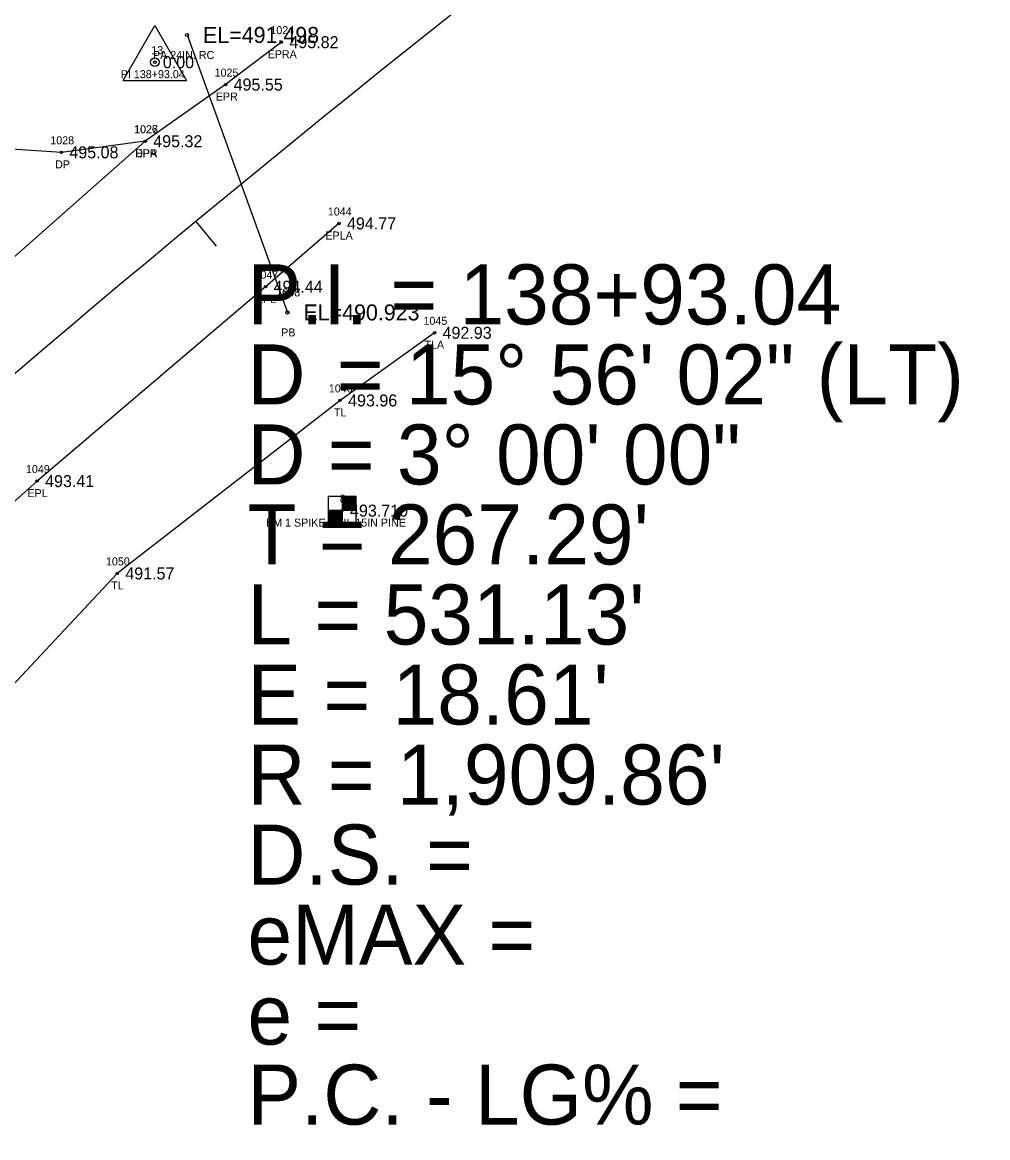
# Model space of a CAD drawing. Extents: x 1740701 to 1743138, y 748181 to 751839.
# Drawn here: x 1742062.9 to 1742183.5, y 750456.4 to 750595.8 of the extents above; entities that cross this region are included whole.
import ezdxf

# ---------------------------------------------------------------- set-up
doc = ezdxf.new("R2010")
doc.units = 0
for name, color, linetype in [('RD_EX_DR_Pipe', 7, 'Continuous'), ('RD_EX_DR_Pipe_txCode', 7, 'Continuous'), ('RD_EX_Driveway', 7, 'Continuous'), ('RD_EX_Driveway_txCode', 7, 'Continuous'), ('RD_EX_Road', 7, 'Continuous'), ('RD_EX_Road_txCode', 7, 'Continuous'), ('RD_EX_TX_Driveway_ELEV', 7, 'Continuous'), ('RD_EX_TX_Road_ELEV', 7, 'Continuous'), ('RD_EX_TX_VEG_ELEV', 7, 'Continuous'), ('RD_EX_VEG', 7, 'Continuous'), ('RD_EX_VEG_txCode', 7, 'Continuous'), ('RD_HC_Cl', 7, 'Continuous'), ('RD_HC_Data', 7, 'Continuous'), ('RD_HC_Data_Tic', 7, 'Continuous'), ('RD_HC_Survey', 7, 'Continuous'), ('RD_HC_Survey_ELEV', 7, 'Continuous'), ('RD_HC_Survey_txCode', 7, 'Continuous'), ('RD_HC_txCode', 7, 'Continuous'), ('RD_SMD_Locator', 7, 'Continuous'), ('RD_TX_Pipe_ElevEX', 7, 'Continuous')]:
    doc.layers.add(name, color=color, linetype=linetype)

msp = doc.modelspace()

# ---------------------------------------------------------------- linework, layer by layer
at = {"layer": 'RD_EX_DR_Pipe'}
msp.add_line((1742083.45, 750594.17), (1742095.99, 750559.5), dxfattribs=at)
at = {"layer": 'RD_EX_Driveway'}
msp.add_lwpolyline([(1742078.23, 750580.89), (1742067.75, 750579.5), (1742055.26, 750580.31), (1742043.56, 750582.25), (1742032.68, 750586.37), (1742011.54, 750590.38), (1741988.47, 750592.64), (1741971.4, 750592.74)], dxfattribs=at)
at = {"layer": 'RD_EX_Road'}
for points in [[(1742095.24, 750593.27), (1742088.27, 750587.97), (1742078.23, 750580.89), (1742049.13, 750555.21), (1742012.94, 750522.73), (1741975.54, 750488.03), (1741940.71, 750452.82), (1741916.22, 750428.67), (1741904.72, 750416.99), (1741884.38, 750395.02), (1741870.75, 750380.27), (1741817.36, 750322.98), (1741803.89, 750307.66), (1741783.86, 750287.33), (1741735.44, 750234.07), (1741718.84, 750214.98), (1741710.25, 750205.58), (1741668.97, 750159.8), (1741635, 750122.49), (1741604.35, 750087.7), (1741600.63, 750085.47)], [(1742102.43, 750570.61), (1742093.26, 750562.71), (1742064.72, 750538.42), (1742027.92, 750505.65), (1741991.25, 750471.83), (1741956.32, 750436.98), (1741921.43, 750401.39), (1741886.79, 750364.93), (1741819.64, 750292.67), (1741751.78, 750219.01), (1741684.42, 750145.59), (1741650.98, 750108.5), (1741637.17, 750092.42), (1741621.17, 750073.94), (1741621.31, 750072.22), (1741619.24, 750070.27)]]:
    msp.add_lwpolyline(points, dxfattribs=at)
at = {"layer": 'RD_EX_VEG'}
msp.add_lwpolyline([(1742114.37, 750556.95), (1742102.57, 750548.5), (1742074.74, 750526.88), (1742042.48, 750492.43), (1742005.49, 750457.25), (1741971.49, 750420.27), (1741936.96, 750386.65), (1741902.94, 750350.76), (1741835.15, 750278.46), (1741766.69, 750206.43), (1741693.82, 750135.64), (1741661.95, 750096.11), (1741631.51, 750044.18), (1741602.3, 750028.04), (1741573.25, 749982.32), (1741544.84, 749941.06), (1741514.68, 749901.47), (1741495.89, 749858.02), (1741462.75, 749819.18), (1741434.73, 749775.9), (1741408.39, 749735.06), (1741355.53, 749651.67)], dxfattribs=at)
at = {"layer": 'RD_HC_Cl'}
msp.add_arc((1743302.33, 749099.61), 1909.86, 121.38831, 137.32219, dxfattribs=at)
at = {"layer": 'RD_HC_Data'}
for p, q in [((1742075.46, 750588.47), (1742079.44, 750595.35)), ((1742079.44, 750595.35), (1742083.4, 750588.47)), ((1742075.46, 750588.47), (1742083.4, 750588.47))]:
    msp.add_line(p, q, dxfattribs=at)
msp.add_circle((1742079.43, 750590.77), 0.529, dxfattribs=at)
at = {"layer": 'RD_HC_Data_Tic'}
msp.add_line((1742084.54, 750570.85), (1742087.09, 750567.77), dxfattribs=at)
at = {"layer": 'RD_HC_Survey'}
for p, q in [((1742102.81, 750536.48), (1742102.81, 750532.98)), ((1742102.83, 750536.48), (1742102.83, 750534.73)), ((1742102.85, 750536.48), (1742102.85, 750534.73)), ((1742102.87, 750536.48), (1742102.87, 750534.73)), ((1742102.9, 750536.48), (1742102.9, 750534.73)), ((1742102.92, 750536.48), (1742102.92, 750534.73)), ((1742102.95, 750536.48), (1742102.95, 750534.73)), ((1742102.97, 750536.48), (1742102.97, 750534.73)), ((1742103, 750536.48), (1742103, 750534.73)), ((1742103.02, 750536.48), (1742103.02, 750534.73)), ((1742103.05, 750536.48), (1742103.05, 750534.73)), ((1742103.07, 750536.48), (1742103.07, 750534.73)), ((1742103.1, 750536.48), (1742103.1, 750534.73)), ((1742103.12, 750536.48), (1742103.12, 750534.73)), ((1742103.15, 750536.48), (1742103.15, 750534.73)), ((1742103.17, 750536.48), (1742103.17, 750534.73)), ((1742103.2, 750536.48), (1742103.2, 750534.73)), ((1742103.22, 750536.48), (1742103.22, 750534.73)), ((1742103.25, 750536.48), (1742103.25, 750534.73)), ((1742103.27, 750536.48), (1742103.27, 750534.73)), ((1742103.3, 750536.48), (1742103.3, 750534.73)), ((1742103.32, 750536.48), (1742103.32, 750534.73)), ((1742103.34, 750536.48), (1742103.34, 750534.73)), ((1742103.37, 750536.48), (1742103.37, 750534.73)), ((1742103.39, 750536.48), (1742103.39, 750534.73)), ((1742103.42, 750536.48), (1742103.42, 750534.73)), ((1742103.44, 750536.48), (1742103.44, 750534.73)), ((1742103.47, 750536.48), (1742103.47, 750534.73)), ((1742103.49, 750536.48), (1742103.49, 750534.73)), ((1742103.52, 750536.48), (1742103.52, 750534.73)), ((1742103.54, 750536.48), (1742103.54, 750534.73)), ((1742103.57, 750536.48), (1742103.57, 750534.73)), ((1742103.59, 750536.48), (1742103.59, 750534.73)), ((1742103.62, 750536.48), (1742103.62, 750534.73)), ((1742103.64, 750536.48), (1742103.64, 750534.73)), ((1742103.67, 750536.48), (1742103.67, 750534.73)), ((1742103.69, 750536.48), (1742103.69, 750534.73)), ((1742103.72, 750536.48), (1742103.72, 750534.73)), ((1742103.74, 750536.48), (1742103.74, 750534.73)), ((1742103.77, 750536.48), (1742103.77, 750534.73)), ((1742103.79, 750536.48), (1742103.79, 750534.73)), ((1742103.82, 750536.48), (1742103.82, 750534.73)), ((1742103.84, 750536.48), (1742103.84, 750534.73)), ((1742103.86, 750536.48), (1742103.86, 750534.73)), ((1742103.89, 750536.48), (1742103.89, 750534.73)), ((1742103.91, 750536.48), (1742103.91, 750534.73)), ((1742103.94, 750536.48), (1742103.94, 750534.73)), ((1742103.96, 750536.48), (1742103.96, 750534.73)), ((1742103.99, 750536.48), (1742103.99, 750534.73)), ((1742104.01, 750536.48), (1742104.01, 750534.73)), ((1742104.04, 750536.48), (1742104.04, 750534.73)), ((1742104.06, 750536.48), (1742104.06, 750534.73)), ((1742104.09, 750536.48), (1742104.09, 750534.73)), ((1742104.11, 750536.48), (1742104.11, 750534.73)), ((1742104.14, 750536.48), (1742104.14, 750534.73)), ((1742104.16, 750536.48), (1742104.16, 750534.73)), ((1742104.19, 750536.48), (1742104.19, 750534.73)), ((1742104.21, 750536.48), (1742104.21, 750534.73)), ((1742104.24, 750536.48), (1742104.24, 750534.73)), ((1742104.26, 750536.48), (1742104.26, 750534.73)), ((1742104.29, 750536.48), (1742104.29, 750534.73)), ((1742104.31, 750536.48), (1742104.31, 750534.73)), ((1742104.33, 750536.48), (1742104.33, 750534.73)), ((1742104.36, 750536.48), (1742104.36, 750534.73)), ((1742104.38, 750536.48), (1742104.38, 750534.73)), ((1742104.41, 750536.48), (1742104.41, 750534.73)), ((1742104.43, 750536.48), (1742104.43, 750534.73)), ((1742104.46, 750536.48), (1742104.46, 750534.73)), ((1742104.48, 750536.48), (1742104.48, 750534.73)), ((1742104.51, 750536.48), (1742104.51, 750534.73)), ((1742104.53, 750536.48), (1742104.53, 750534.73)), ((1742104.56, 750534.73), (1742101.06, 750534.73)), ((1742101.06, 750534.73), (1742101.06, 750532.98)), ((1742101.08, 750534.73), (1742101.08, 750532.98)), ((1742101.11, 750534.73), (1742101.11, 750532.98)), ((1742101.13, 750534.73), (1742101.13, 750532.98)), ((1742101.16, 750534.73), (1742101.16, 750532.98)), ((1742101.18, 750534.73), (1742101.18, 750532.98)), ((1742101.21, 750534.73), (1742101.21, 750532.98)), ((1742101.23, 750534.73), (1742101.23, 750532.98)), ((1742101.26, 750534.73), (1742101.26, 750532.98)), ((1742101.28, 750534.73), (1742101.28, 750532.98)), ((1742101.3, 750534.73), (1742101.3, 750532.98)), ((1742101.33, 750534.73), (1742101.33, 750532.98)), ((1742101.35, 750534.73), (1742101.35, 750532.98)), ((1742101.38, 750534.73), (1742101.38, 750532.98)), ((1742101.4, 750534.73), (1742101.4, 750532.98)), ((1742101.43, 750534.73), (1742101.43, 750532.98)), ((1742101.45, 750534.73), (1742101.45, 750532.98)), ((1742101.48, 750534.73), (1742101.48, 750532.98)), ((1742101.5, 750534.73), (1742101.5, 750532.98)), ((1742101.53, 750534.73), (1742101.53, 750532.98)), ((1742101.55, 750534.73), (1742101.55, 750532.98)), ((1742101.58, 750534.73), (1742101.58, 750532.98)), ((1742101.6, 750534.73), (1742101.6, 750532.98)), ((1742101.63, 750534.73), (1742101.63, 750532.98)), ((1742101.65, 750534.73), (1742101.65, 750532.98)), ((1742101.68, 750534.73), (1742101.68, 750532.98)), ((1742101.7, 750534.73), (1742101.7, 750532.98)), ((1742101.73, 750534.73), (1742101.73, 750532.98)), ((1742101.75, 750534.73), (1742101.75, 750532.98)), ((1742101.78, 750534.73), (1742101.78, 750532.98)), ((1742101.8, 750534.73), (1742101.8, 750532.98)), ((1742101.82, 750534.73), (1742101.82, 750532.98)), ((1742101.85, 750534.73), (1742101.85, 750532.98)), ((1742101.87, 750534.73), (1742101.87, 750532.98)), ((1742101.9, 750534.73), (1742101.9, 750532.98)), ((1742101.92, 750534.73), (1742101.92, 750532.98)), ((1742101.95, 750534.73), (1742101.95, 750532.98)), ((1742101.97, 750534.73), (1742101.97, 750532.98)), ((1742102, 750534.73), (1742102, 750532.98)), ((1742102.02, 750534.73), (1742102.02, 750532.98)), ((1742102.05, 750534.73), (1742102.05, 750532.98)), ((1742102.07, 750534.73), (1742102.07, 750532.98)), ((1742102.1, 750534.73), (1742102.1, 750532.98)), ((1742102.12, 750534.73), (1742102.12, 750532.98)), ((1742102.15, 750534.73), (1742102.15, 750532.98)), ((1742102.17, 750534.73), (1742102.17, 750532.98)), ((1742102.2, 750534.73), (1742102.2, 750532.98)), ((1742102.22, 750534.73), (1742102.22, 750532.98)), ((1742102.25, 750534.73), (1742102.25, 750532.98)), ((1742102.27, 750534.73), (1742102.27, 750532.98)), ((1742102.29, 750534.73), (1742102.29, 750532.98)), ((1742102.32, 750534.73), (1742102.32, 750532.98)), ((1742102.34, 750534.73), (1742102.34, 750532.98)), ((1742102.37, 750534.73), (1742102.37, 750532.98)), ((1742102.39, 750534.73), (1742102.39, 750532.98)), ((1742102.42, 750534.73), (1742102.42, 750532.98)), ((1742102.44, 750534.73), (1742102.44, 750532.98)), ((1742102.47, 750534.73), (1742102.47, 750532.98)), ((1742102.49, 750534.73), (1742102.49, 750532.98)), ((1742102.52, 750534.73), (1742102.52, 750532.98)), ((1742102.54, 750534.73), (1742102.54, 750532.98)), ((1742102.57, 750534.73), (1742102.57, 750532.98)), ((1742102.59, 750534.73), (1742102.59, 750532.98)), ((1742102.62, 750534.73), (1742102.62, 750532.98)), ((1742102.64, 750534.73), (1742102.64, 750532.98)), ((1742102.67, 750534.73), (1742102.67, 750532.98)), ((1742102.69, 750534.73), (1742102.69, 750532.98)), ((1742102.72, 750534.73), (1742102.72, 750532.98)), ((1742102.74, 750534.73), (1742102.74, 750532.98)), ((1742102.77, 750534.73), (1742102.77, 750532.98)), ((1742102.79, 750534.73), (1742102.79, 750532.98))]:
    msp.add_line(p, q, dxfattribs=at)
msp.add_lwpolyline([(1742104.56, 750536.48), (1742101.06, 750536.48), (1742101.06, 750532.98), (1742104.56, 750532.98)], close=True, dxfattribs=at)
at = {"layer": 'RD_SMD_Locator'}
for centre, radius in [((1742083.45, 750594.17), 0.2), ((1742095.24, 750593.27), 0.15), ((1742079.43, 750590.77), 0.15), ((1742088.27, 750587.97), 0.15), ((1742078.23, 750580.89), 0.15), ((1742078.23, 750580.89), 0.15), ((1742067.75, 750579.5), 0.15), ((1742102.43, 750570.61), 0.15), ((1742093.26, 750562.71), 0.15), ((1742095.99, 750559.5), 0.2), ((1742114.37, 750556.95), 0.15), ((1742102.57, 750548.5), 0.15), ((1742064.72, 750538.42), 0.15), ((1742102.81, 750534.73), 0.15), ((1742074.74, 750526.88), 0.15)]:
    msp.add_circle(centre, radius, dxfattribs=at)

# ---------------------------------------------------------------- texts
at = {"layer": 'RD_EX_DR_Pipe_txCode'}
for s, p in [('PA 24IN. RC', (1742079.2, 750591.17)), ('1048', (1742094.61, 750561.5)), ('PB', (1742095.21, 750556.5))]:
    msp.add_text(s, height=1, dxfattribs=at).set_placement(p)
at = {"layer": 'RD_EX_Driveway_txCode'}
for s, p in [('1027', (1742076.85, 750581.89)), ('1028', (1742066.37, 750580.5)), ('DPA', (1742076.97, 750578.89)), ('DP', (1742066.97, 750577.5))]:
    msp.add_text(s, height=1, dxfattribs=at).set_placement(p)
at = {"layer": 'RD_EX_Road_txCode'}
for s, p in [('1024', (1742093.86, 750594.27)), ('EPRA', (1742093.52, 750591.27)), ('1025', (1742086.89, 750588.97)), ('EPR', (1742087.04, 750585.97)), ('1026', (1742076.83, 750581.89)), ('EPR', (1742077.01, 750578.89)), ('1044', (1742101.04, 750571.61)), ('EPLA', (1742100.73, 750568.61)), ('1047', (1742091.88, 750563.71)), ('EPL', (1742092.06, 750560.71)), ('1049', (1742063.33, 750539.42)), ('EPL', (1742063.52, 750536.42))]:
    msp.add_text(s, height=1, dxfattribs=at).set_placement(p)
at = {"layer": 'RD_EX_TX_Driveway_ELEV'}
for s, p in [('495.32', (1742079.23, 750580.14)), ('495.08', (1742068.75, 750578.75))]:
    msp.add_text(s, height=1.5, dxfattribs=at).set_placement(p)
at = {"layer": 'RD_EX_TX_Road_ELEV'}
for s, p in [('495.82', (1742096.24, 750592.52)), ('495.55', (1742089.27, 750587.22)), ('495.32', (1742079.23, 750580.14)), ('494.77', (1742103.43, 750569.86)), ('494.44', (1742094.26, 750561.96)), ('493.41', (1742065.72, 750537.67))]:
    msp.add_text(s, height=1.5, dxfattribs=at).set_placement(p)
at = {"layer": 'RD_EX_TX_VEG_ELEV'}
for s, p in [('492.93', (1742115.37, 750556.2)), ('493.96', (1742103.57, 750547.75)), ('491.57', (1742075.74, 750526.13))]:
    msp.add_text(s, height=1.5, dxfattribs=at).set_placement(p)
at = {"layer": 'RD_EX_VEG_txCode'}
for s, p in [('1045', (1742112.99, 750557.95)), ('TLA', (1742113.11, 750554.95)), ('1046', (1742101.16, 750549.5)), ('TL', (1742101.8, 750546.5)), ('1050', (1742073.32, 750527.88)), ('TL', (1742073.97, 750524.88))]:
    msp.add_text(s, height=1, dxfattribs=at).set_placement(p)
at = {"layer": 'RD_HC_Data'}
for s, p in [('P.I. = 138+93.04', (1742091, 750558)), ('    = 15%%d 56\' 02" (LT)', (1742091, 750548)), ('D', (1742091, 750548)), ('D = 3%%d 00\' 00"', (1742091, 750538)), ("T = 267.29'", (1742091, 750528)), ("L = 531.13'", (1742091, 750518)), ("E = 18.61'", (1742091, 750508)), ("R = 1,909.86'", (1742091, 750498)), ('D.S. = ', (1742091, 750488)), ('eMAX = ', (1742091, 750478)), ('e = ', (1742091, 750468)), ('P.C. - LG% = ', (1742091, 750458))]:
    msp.add_text(s, height=7.5, dxfattribs=at).set_placement(p)
at = {"layer": 'RD_HC_Survey_ELEV'}
for s, p in [('0.00', (1742080.43, 750590.02)), ('493.710', (1742103.81, 750533.98))]:
    msp.add_text(s, height=1.5, dxfattribs=at).set_placement(p)
at = {"layer": 'RD_HC_Survey_txCode'}
for s, p in [('8', (1742102.52, 750535.73)), ('BM 1 SPIKE NAIL 15IN PINE', (1742093.32, 750532.73))]:
    msp.add_text(s, height=1, dxfattribs=at).set_placement(p)
at = {"layer": 'RD_HC_txCode'}
for s, p in [('13', (1742078.99, 750591.77)), ('PI 138+93.04', (1742075.17, 750588.77))]:
    msp.add_text(s, height=1, dxfattribs=at).set_placement(p)
at = {"layer": 'RD_TX_Pipe_ElevEX'}
for s, p in [('EL=491.498', (1742085.45, 750593.17)), ('EL=490.923', (1742097.99, 750558.5))]:
    msp.add_text(s, height=2, dxfattribs=at).set_placement(p)

doc.saveas('drawing.dxf')
